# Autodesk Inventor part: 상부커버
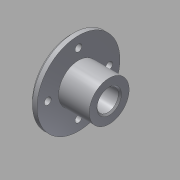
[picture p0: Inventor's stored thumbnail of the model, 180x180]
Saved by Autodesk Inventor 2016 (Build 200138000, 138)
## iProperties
Created: 2015-09
Part Number: 상부커버
Material: 알루미늄 6061
Document SubType Name: Modeling
Designer: mduedu
Density: 1 g/cm^3
Appearance: 알루미늄 - 평지
Author: mduedu
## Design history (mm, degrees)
sketch "스케치1"
  geometry: L1 (-12.5, 0)-(12.5, 0); L2 (-12.5, 0)-(-12.5, 27); L3 (-12.5, 27)-(-7.5, 27); L4 (-7.5, 27)-(-7.5, 13); L5 (-7.5, 13)-(12.5, 13); L6 (12.5, 13)-(12.5, 0); 2 further points
  constraints: 12 end point, 2 parallel, 2 perpendicular, 1 coincident, 1 horizontal, 1 midpoint, 1 vertical
  dimensions: "d0" = 25 distance of L1.start L1.end; "d2" = 5 distance of L2.end L3.end; "d3" = 26 diameter of L5 L1; "d4" = 54 diameter of L3 L1
revolve "회전1" sketch "스케치1" stored, may be unused: angle "d5" = 90 deg
hole "구멍1" diameter "d8" = 14; stored, may be unused: countersink angle "d12" = 90 deg, drill point angle "d14" = 118 deg; dims "d6" = 10, "d7" = 10, "d9" = 6, "d10" = 4, "d11" = 2, "d13" = 8
chamfer "모따기1" distance "d15" = 1; stored, may be unused: second distance "d16" = 2, angle "d17" = 45 deg
chamfer "모따기2" distance "d18" = 2; stored, may be unused: second distance "d19" = 2, angle "d20" = 45 deg
sketch "스케치2" dims "d21" = 40
  geometry: 6 further points
  constraints: 2 vertical alignment, 1 coincident, 7 other
  dimensions: "d25" = 360 deg dimension on point (0, 0) point (0, 20) (derived)
sketch "스케치3"
  geometry: 4 further points
hole "구멍2" sketch "스케치3" at (0, 20), (-20, 0), (20, 0), (0, -20) diameter "d27" = 4.5; stored, may be unused: countersink angle "d31" = 90 deg, drill point angle "d33" = 0 deg; dims "d28" = 6, "d29" = 4, "d30" = 2, "d32" = 8
node "솔리드1"
